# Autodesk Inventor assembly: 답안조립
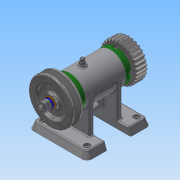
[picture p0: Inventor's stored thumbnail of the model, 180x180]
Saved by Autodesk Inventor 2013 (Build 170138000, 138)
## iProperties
Created: 2016-07
Part Number: 답안조립
Document SubType Name: Assembly
Designer: Administrator
Author: Administrator
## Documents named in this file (16)
- C:\Users\Administrator\Desktop\460708V1016\답안조립.iam
- C:\Users\Administrator\Desktop\460708V1016\1-본체.ipt
- C:\Users\Administrator\Desktop\460708V1016\V벨트풀리.ipt
- C:\Users\Administrator\Desktop\460708V1016\너트 M 8.ipt
- C:\Users\Administrator\Desktop\460708V1016\니플 M 6 x 0.75.ipt
- C:\Users\Administrator\Desktop\460708V1016\베어링 15 x 32 x 9.ipt
- C:\Users\Administrator\Desktop\460708V1016\볼트 M 6 x 8.ipt
- C:\Users\Administrator\Desktop\460708V1016\볼트 M4 x 12.ipt
- C:\Users\Administrator\Desktop\460708V1016\스퍼기어.ipt
- C:\Users\Administrator\Desktop\460708V1016\스프링와셔 8.ipt
- C:\Users\Administrator\Desktop\460708V1016\오일 실 15 25 7.ipt
- C:\Users\Administrator\Desktop\460708V1016\와셔 6x11.5.ipt
- C:\Users\Administrator\Desktop\460708V1016\와셔 8x17.ipt
- C:\Users\Administrator\Desktop\460708V1016\축.ipt
- C:\Users\Administrator\Desktop\460708V1016\커버.ipt
- C:\Users\Administrator\Desktop\460708V1016\키 3 x 3 x 12.ipt
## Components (12 placed, 4 different names)
1. 1-본체:1
2. V벨트풀리:1
3. KS B 2023 6002 - 15 x 32 x 9:1
4. ISO 4762 M4 x 12:1
5. KS B 2023 6002 - 15 x 32 x 9:2
6. ISO 4762 M4 x 12:2
7. ISO 4762 M4 x 12:3
8. ISO 4762 M4 x 12:4
9. ISO 4762 M4 x 12:5
10. ISO 4762 M4 x 12:6
11. ISO 4762 M4 x 12:7
12. ISO 4762 M4 x 12:8
